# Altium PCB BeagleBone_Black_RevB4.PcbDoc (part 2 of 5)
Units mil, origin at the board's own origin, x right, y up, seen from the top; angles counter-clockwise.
Board outline 3401 x 2151 mil, 6 copper layers (TOP, LYR2_GND, LYR3, LYR4, LYR5_PWR, BOTTOM), stack 62 mil thick; 381 components, 310 nets, 1705 pads, 850 vias.
Unrouted connection lines stored in the file: 1.
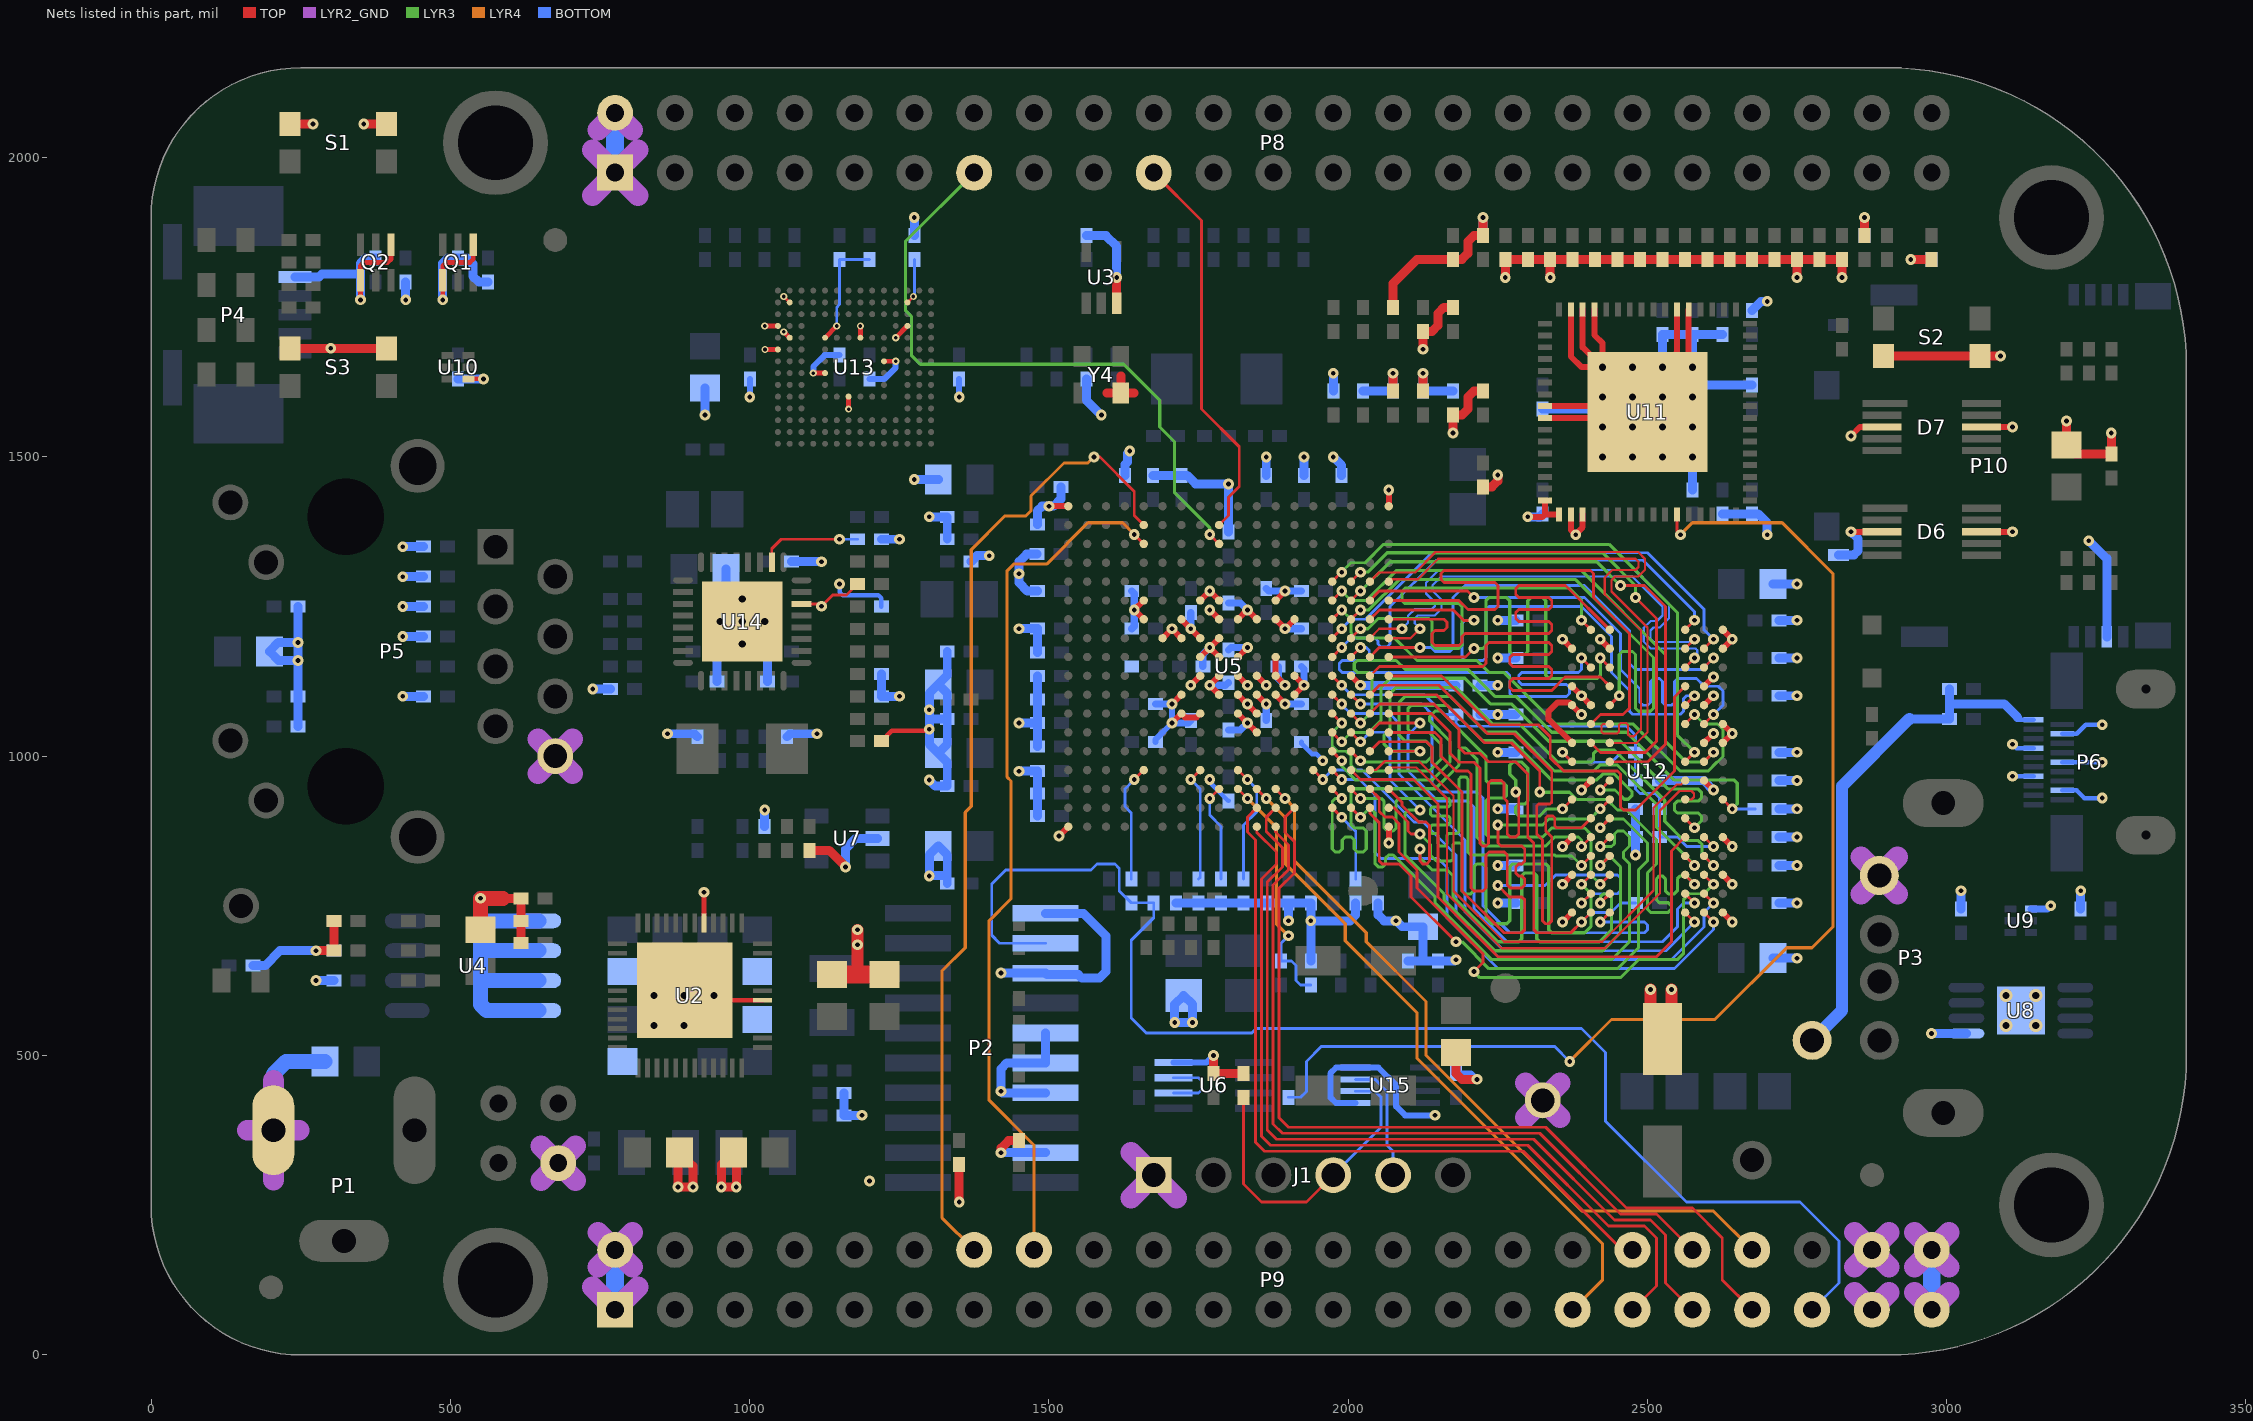
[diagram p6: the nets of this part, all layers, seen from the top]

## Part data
C1 C2 C118 C122 C126 C133: library part CAP_4.7uF_X5R_6.3V_10%_0603, "CAP CER 10UF 10V Y5V 0805"
C3: library part CAP_10uF_Y5V_10V_10%_0805, "CAP CER 0.1UF 6.3V 10% X5R 0402"
C4 C7 C8 C9 C10 C11 C12 C13 C14 C15 C39 C40 C55 C62 C77 C95 C96 C153: library part CAP_10uF_Y5V_10V_10%_0805, "CAP CER 10UF 10V Y5V 0805"
C16 C17 C18: library part CAP_2.2uF_X5R_6.3V_10%_0402, "CAP CER 2.2UF 6.3V 10% X5R 0402"
C19: library part CAP_2.2uF_X5R_6.3V_10%_0402, "CAP CER 470PF 50V 10% X7R 0402"
C20 C27 C28 C29 C30 C31 C33 C35 C36 C37 C38 C41 C42 C43 C44 C45 C46 C47 C48 C49 C50 C51 C52 C53 C54 C56 C57 C58 C59 C60 C61 C63 C64 C65 C66 C67 C68 C69 C70 C71 C72 C73 C74 C75 C76 C78 C79 C80 C81 C82 C83 C84 C85 C86 C87 C88 C92 C93 C94 C97 C98 C99 C100 C101 C102 C103 C105 C106 C131 C132 C135 C152 C154 C155 C158 C159: library part "CAP_0.1uF_X7R_16V_10% 0402", "CAP CER 0.1UF 6.3V 10% X5R 0402"
C21 C22 C25 C26: library part CAP_18PF_COG_50V_5%_0402, "CAP CER 18PF 50V 5% NP0 0402"
C24 C89 C90 C91 C104 C134: library part CAP_1.0UF_X5R_10V_10%_0402, "CAP CER 1UF 10V 10% X5R 0402"
C32: library part CAP_0.001_X7R_50V_5%_0402, "CAP CER 1000PF 16V 10% X7R 0402"
C34: library part "CAP SMD", "CAP ALUM 100UF 6.3V 20% SMD"
C107 C108 C109 C110 C111 C112 C113 C114 C115 C116 C117 C119 C120 C121 C124: library part CAP_0.01uf_X7R_16V_10%_0402, "CAP CER 0.1UF 6.3V 10% X5R 0402"
C123: library part "CAP SMD", "CAP CER 1000PF 16V 10% X7R 0402"
C125 C144 C146 C148 C151: library part "CAP SMD", "CAP CER 2.2UF 6.3V 10% X5R 0402"
C127 C128 C129 C130 C145 C147 C149 C150: library part "CAP SMD", "CAP CER 0.1UF 6.3V 10% X5R 0402"
C136: library part 470pF/5%/50V/C0G/0603_0, "CAP CER 470PF 50V 10% X7R 0402"
C137 C138 C139 C140: library part CAP_0402_100pF_COG_50V, "CAP CER 15PF 50V 5% NP0 0402"
C141: library part CAP_0402_0.1uf_X5R_10V, "CAP CER 0.022UF 10V 10% X7R 0402"
C142 C143: library part CAP_30PF_COG_50V_5%_0402, "CAP CER 30PF 50V 5% NP0 0402"
C156 C157 C160 C161 C162 C163 C164 C165 C166 C167 C168 C169 C170 C171 C172 C173: library part "CAP SMD", "CAP CER 47PF 50V 5% NP0 0402"
D1 D2 D3 D4 D5: library part LED_LTST-C150GKT, "LED GREEN CLEAR 0805 SMD"
D6 D7: library part 32CTQ030/TO_1, "DIODE ESD PROT HDMI 10TSSOP"
D8: library part Zener, "DIODE SCHOTTKY 40V 120MA SOD323"
FB1 FB2 FB3 FB4 FB7: library part FER_180_200_0, "FERRITE 800MA 150 OHM 0805 SMD"
FB5: library part IND, "FERRITE 800MA 150 OHM 0805 SMD"
FB8: library part FER_180_200_0, "RES .10 OHM 1/8W 5% 0805"
J1: library part HDR_6x1, "CONN HEADER 6POS, VERTICAL,  .100 STR TIN"
L1: library part IND_2.2uH_2.6A_10%_SMD, "Inductor 2.2uH smt 2.6A, 58 milliohm"
L2 L3: library part IND_2.2uH_2.6A_10%_SMD, "INDUCTOR 2.2UH 20% 1300MA 1008"
P1: library part Power_Jack, "CONN PWR JACK 2.1X5.5MM HIGH CUR"
P2: library part HDR_10x2_CJTAG, "Dual Line Header 10x2pin Tin"
P3: library part CONN_54819-0578_2, "CONN RCPT USB TYPE A R/A PCB"
P4: library part MINI-USB-AB-SOCKET, "CONN RCPT USB MINI B R/A SMD"
P5: library part CONN_RJ45_MAG_WE_0, "WE-RJ45 LAN Transformer"
P6: library part "Micro HDMI", "CONN HDMI RECPT 19POS SMT R/A"
P8 P9: library part HDR_46_F_2_0.1_0.1, "CONN HEADER FMAL 46PS.1\" DL GOLD"
P10: library part microSD_CONN_2, "CONN MICRO SD R/A PUSH-PUSH SMD"
Q1 Q2: library part RN1907, "TRANS PREBIASED DUAL NPN SOT363"
R1 R55 R56 R57 R58 R59 R60 R61 R62 R63 R64 R65 R66 R67 R68 R69 R70 R76 R77 R78 R79 R80 R81 R82 R83 R84 R85 R86 R87 R88 R89 R90 R91 R92 R93 R94 R95 R165: library part RES_100K_1/16W_1%_0402, "RES 100K OHM 1/16W 1% 0402 SMD"
R3 R4 R119: library part RES_1.5K_1/16W_5%_0402, "RES 1.50K OHM 1/16W 1% 0402 SMD"
R5 R6 R7 R8 R9 R19 R20 R27 R49 R50 R51 R137 R140 R142 R159 R160 R161 R162: library part RES_0_1/16W_1%_0402, "RES 0.0 OHM 1/16W 0402 SMD"
R10: library part RES_470_1/10W_5%_0402, "RES 470K OHM 1/16W 1% 0402 SMD"
R11: library part RES_470_1/10W_5%_0402, "RES 280K OHM 1/16W 1% 0402 SMD"
R12 R71 R72 R73 R74: library part RES_470_1/10W_5%_0402, "RES 820 OHM 1/10W 5% 0402 SMD"
R14 R54 R96 R98 R100 R101 R102 R103 R104 R105 R106 R107 R108 R109 R110 R111 R115 R116 R117 R118 R135 R145 R150 R151 R152 R153 R154 R155 R156 R157: library part RES_10K_1/16W_1%_0402, "RES 10K OHM 1/16W 5% 0402 SMD"
R17: library part RES_1M_1/16W_1%_0402, "Resistor 1Mohm 1/16W 1% 0402"
R18 R21 R28 R45 R46 R47 R48 R167: library part RES_33_0402, "RES 33 OHM 1/16W 5% 0402 SMD"
R22 R120 R121 R122 R123: library part RES_4.7K_0402, "RES 49.9 OHM 1/16W 1% 0402 SMD"
R23 R24 R25: library part RES_4.7K_0402, "RES 4.75K 1/16W 1% 0402 SMD"
R26 R163 R164: library part RES_4.75K_1/16W_1%_0402, "RES 4.75K OHM 1/16W 1% 0402 SMD"
R52 R53 R148 R158: library part "RES SMD", "RES 10K OHM 1/16W 5% 0402 SMD"
R75: library part "RES SMD", "RES 100 OHM 1/10W 5% 0402 SMD"
R97 R112 R113 R114: library part RES_10K_1/16W_1%_0402, "RES 1.50K OHM 1/16W 1% 0402 SMD"
R99: library part RES_10K_1/16W_1%_0402, "RES 240 OHM 1/10W 5% 0402 SMD"
R124: library part RES_10K_1/16W_1%_0402, "Resistor 10Kohm 1/16W 1% 0402"
R125 R126 R129 R134 R138: library part 100-1/10W-1%-0603_4, "RES 100 OHM 1/10W 5% 0402 SMD"
R127 R128 R131 R133 R139: library part RES_100_1/10W_5%_0402, "RES 100 OHM 1/10W 5% 0402 SMD"
R130 R132: library part RES_470_1/10W_5%_0402, "RES 470 OHM 1/10W 5% 0402 SMD"
R136: library part RES_0.1_0805, "RES .10 OHM 1/8W 5% 0805"
R141: library part RES_1M_1/16W_1%_0402, "RES 1M OHM 1/16W 1% 0402 SMD"
R143: library part RES_10K_1/16W_1%_0402, "RES 10 OHM 1/16W 1% 0402 SMD"
R144: library part RES_12.1K_1/16W_1%_0402, "RES 12.1K OHM 1/16W 1% 0402 SMD"
R146 R147: library part "RES SMD", "RES 1.50K OHM 1/16W 1% 0402 SMD"
R149: library part "RES SMD", "RES 0.0 OHM 1/16W 0402 SMD"
R166: library part "RES SMD", "RES 27.0K OHM 1/16W 1% 0402 SMD"
RT1: library part PTC, "POLYSWITCH PTC RESET 0.1A"
S1 S2 S3: library part KMR2, "Microminiature Tact Switch for SMT"
U2: library part PWR_TPS65217_2, "IC PMIC BATT PWR SYST 48VQFN"
U3: "IC INVERTER SINGLE 1INPUT SC705"
U4: "IC LDO VOLT REG 500MA 8-SOIC"
U5: "SubArctic Cortex A8 Processor 15x15"
U6: "SINGLE  POSITIVE-EDGE-TRIGGERED  D-TYPE  FLIP-FLOP WITH  CLEAR  AND  PRESET"
U7: "IC EEPROM 32KBIT 400KHZ SOT23-5"
U8: library part TPS2061_0, "IC 1.5A PWR DIST SWITCH 8-SOIC"
U9 U10: library part PROT_TPD4S012, "ESD 4channel USB Interface"
U11: "IC HDMI TRANSMITTER 64-HVQFN"
U12: library part MT41K256M16HA, "DDR2 SDRAM 2Gb (256Mx8)"
U13: library part eMMC, "Flash Card 2G-byte 3.3V MultiMedia Card 153-Pin WFBGA"
U14: library part "LAN8710 QFN32_1", "Ethernet ICs 10/100 Ethernet XCVR w/HPAutoMDIX FlexPwr"
U15: "IC BUFF/DVR TRI-ST DL 8VSSOP"
Y1: library part CRYS_32_768KHz_SMD32, "CRYSTAL 32.768KHZ 12.5PF SMD"
Y2: library part CRYS_24MHz_SCC, "CRYSTAL 24.000MHZ 18PF SMD"
Y3: library part "Suntsu ITEMP 25MHz _0.005% 20pf"
Y4: library part ASDMB

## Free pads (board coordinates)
  round 40 all layers, no hole mask+40: 1(200,112.5) 1(675,1862.5) 1(2875,300)

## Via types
v1: diameter 18, hole 8, TOP to BOTTOM, tented both sides, 793 vias
v2: diameter 22, hole 12, TOP to BOTTOM, tented both sides, 30 vias
v3: diameter 12, hole 6, TOP to BOTTOM, tented both sides, 27 vias

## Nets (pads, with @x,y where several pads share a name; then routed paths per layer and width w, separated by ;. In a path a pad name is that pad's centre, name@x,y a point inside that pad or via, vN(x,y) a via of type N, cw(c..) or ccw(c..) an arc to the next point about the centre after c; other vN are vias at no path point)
12M_LOOP: U6.2 U6.3 | length 113.7
  BOTTOM w4.75: U6.2@1708,437.2 1750,437.2 1755,442.2 1755,457.8 1750,462.8 U6.3@1708,462.8
12MHZ: R21.2 U11.27 | length 2002.7
  TOP w4.75: U11.27@2549.21,1403.74 2549.21,1375.79 v1(2555,1370)
  LYR4 w5.25: v1(2370,490) 2440,560 2612.5,560 2732.5,680 2775,680 2810,715 2810,1305 2725,1390 2575,1390 v1(2555,1370)
  BOTTOM w4.75: R21.2@1900,430 1920,430 1930,440 1930,490 1955,515 2345,515 v1(2370,490)
AIN0: P9.39 U5.B6 | length 1506.2
  TOP w4.75: U5.B6@1910.24,913.78 1894.51,898.05 1894.51,872.49 1910,857 1910,805 1884.26,779.26 1884.26,395.74 1900,380 2330,380 2465,245 2575,245 2625,195 2625,125 P9.39@2675,75
AIN1: P9.40 U5.C7 | length 1229
  TOP w4.75: U5.C7@1878.74,945.28 v1(1894.5,929.5)
  LYR4 w5.25: v1(1894.5,929.5) 1910,914 1910,825 2019.01,715.99 2019.12,715.99 2030,705.11 2030,690 2130,590 2130,500 2390,240 2610,240 P9.40@2675,175
AIN2: P9.37 U5.B7 | length 1448.2
  TOP w4.75: U5.B7@1878.74,913.78 1862.97,898.01 1862.97,874.03 1890,847 1890,815 1864.76,789.76 1864.76,375.24 1880,360 2310,360 2445,225 2505,225 2530,200 2530,120 P9.37@2575,75
AIN3: P9.38 U5.A7 | length 1304
  TOP w4.75: U5.A7@1878.74,882.28 1878.74,873.26 1900.25,851.75 1900.25,810.25 1874.51,784.51 1874.51,385.49 1890,370 2320,370 2455,235 2515,235 P9.38@2575,175
AIN4: P9.33 U5.C8 | length 1130.3
  TOP w4.75: U5.C8@1847.24,945.28 v1(1863,929.5)
  LYR4 w5.25: v1(1863,929.5) 1895,897.5 1895,820 1995,720 1995,691.51 2115,571.51 2115,495 2425,185 2425,125 P9.33@2375,75
AIN5: P9.36 U5.B8 | length 1275.4
  TOP w4.75: U5.B8@1847.24,913.78 1831.51,898.05 1831.51,873.49 1845,860 1845,355 1860,340 2292.86,340 2457.86,175 P9.36@2475,175
AIN6: P9.35 U5.A8 | length 1408.2
  TOP w4.75: U5.A8@1847.24,882.28 1847.24,872.76 1880,840 1880,820 1855,795 1855,365 1870,350 2300,350 2435,215 2495,215 2515,195 2515,115 P9.35@2475,75
AIN7: R163.2 R164.1 U5.C9 | length 409.1
  TOP w4.75: U5.C9@1815.75,945.28 v1(1831.5,929.5)
  LYR4 w5.25: v1(1831.5,929.5) 1880,881 1880,720 v1(1900,700)
  BOTTOM w4.75: v1(1900,700) 1887.5,687.5 R163.2@1887.5,657.5 1905,657.5 1912.5,650 1912.5,625 1920,617.5 R164.1@1937.5,617.5
B_UART0_RX: J1.4 R165.1 U15.2 | length 536.4
  TOP w4.75: R165.1@1825,430 1825,285 1855,255 1930,255 J1.4@1975,300
  BOTTOM w4.75: J1.4@1975,300 2055,380 2055,430 2044.8,440.2 U15.2@2012,440.2
B_UART0_TX: J1.5 U15.3 | length 205.3
  BOTTOM w4.75: U15.3@2012,459.8 2045.2,459.8 2065,440 2065,350 2075,340 J1.5@2075,300
CAP_VBB_MPU: C91.1 U5.C10 | length 164.7
  TOP w4.75: v1(1768.5,929.5) 1768.98,930 U5.C10@1784.25,945.28
  BOTTOM w4.75: v1(1768.5,929.5) 1768.5,901.5 1787.5,882.5 C91.1@1787.5,795
CAP_VDD_SRAM_CORE: C89.1 U5.D9 | length 204
  TOP w4.75: U5.D9@1815.75,976.77 v1(1831.5,961)
  BOTTOM w4.75: C89.1@1825,795 1825,885 1847.25,907.25 1847.25,945.25 v1(1831.5,961)
CAP_VDD_SRAM_MPU: C90.1 U5.D11 | length 196
  TOP w4.75: v1(1737,961) U5.D11@1752.76,976.77
  BOTTOM w4.75: v1(1737,961) 1752.76,945.24 1752.76,797.76 C90.1@1750,795
CLKOUT2: P2.18 P9.41 R19.2 R20.1 | length 2266.5
  BOTTOM w4.75: P2.18@1494,687.5 1417.5,687.5 1404.26,700.74 1404.26,786.52 1427.74,810 1570,810 1580,820 1610,820 1617.5,812.5 1617.5,775 R19.2@1637.5,755 R20.1@1675,755 1675,730 1637.5,692.5 1637.5,562.5 1662.5,537.5 1838.71,537.5 1846.21,545 2390,545 2430,505 2430,390 2565,255 2755,255 2820,190 2820,120 P9.41@2775,75
CLKOUT_SRC: R19.1 U5.D14 | length 199.3
  TOP w4.75: v1(1642.5,961) U5.D14@1658.27,976.77
  BOTTOM w4.75: R19.1@1637.5,795 1637.5,905 1626.74,915.76 1626.74,945.24 v1(1642.5,961)
CRS: R139.2 U14.14 | length 110.4
  TOP w4.75: U14.14@1086.5,1254.55 1116.04,1254.55 v1(1120,1250.59) 1138.67,1269.26 1161.76,1269.26 R139.2@1180,1287.5
DDR_A0: U5.F3 U12.N3 | length 920.1
  TOP w4.75: U5.F3@2004.72,1039.76 v1(2020.5,1024)
  LYR3 w5.25: v1(2120,910) 2100,910 2095,905 2095,835 2160,770 2160,760 2245,675 2425,675 2455,705 2455,815 2440,830 2433.75,830 v1(2421.25,817.5)
  BOTTOM w4.75: v1(2020.5,1024) 2036.5,1040 2060,1040 2070,1030 2070,960 v1(2120,910)
DDR_A1: U5.H1 U12.P7 | length 924.8
  TOP w4.75: U5.H1@2067.72,1102.76 2147.24,1102.76 2227.5,1022.5 2272.5,1022.5 2320,975 v1(2320,940)
  LYR3 w4.75: 2370,939.75 2381.99,927.76 2428.1,927.76
  LYR3 w5.25: v1(2320,940) 2320.25,939.75 2370,939.75 ; 2428.1,927.76 2432.24,927.76 2450,910 2465,910 2515,860 2515,820 2500,805 2500,743.99 2505,738.99 2535,738.99 2540,743.99 2540,750 2535,755 2520,755 2515,760 2515,795 2520,800 2525,800 2530,795 2530,775 2535,770 2545,770 2550,775 2550,795 2555,800 2564.75,800 v1(2578.75,786)
DDR_A2: U5.E4 U12.P3 | length 919.5
  TOP w4.75: U5.E4@1973.23,1008.27 v1(1989,992.5)
  LYR3 w4.75: 2405.51,869.49 2405.51,801.74 v1(2421.25,786)
  LYR3 w5.25: v1(1989,992.5) 1989,983.61 2012.61,960 2140,960 2170,990 2170,1025 2136.04,1058.96 2136.04,1066.04 2145.75,1075.75 2154.25,1075.75 2230,1000 2230,960 2235,955 2260,955 2264.01,950.99 2264.01,934.01 2260,930 2235,930 2230,925 2230,870 2235,865 2325,865 2340,880 2395,880 2405.51,869.49
DDR_A3: U5.C3 U12.N2 | length 921.3
  TOP w4.75: U5.C3@2004.72,945.28 v1(2020.5,929.5)
  LYR3 w4.75: 2346.76,833.24 2374.01,833.24 v1(2389.75,817.5)
  LYR3 w5.25: v1(2020.5,929.5) 2055,929.5 2060,924.5 2060,880 2065,875 2075,875 2080,880 2080,924.5 2085,929.5 2167,929.5 2170,926.5 2170,918 2167,915 2140.5,915 2137.5,912 2137.5,903 2140.5,900 2167,900 2170,897 2170,888 2167,885 2140.5,885 2137.5,882 2137.5,873.99 2140.5,870.99 2147,870.99 2150,867.99 2150,853 2153,850 2162,850 2165,853 2165,867.99 2168,870.99 2182,870.99 2185,873.99 2185,962 2188,965 2197,965 2200,962 2200,840 2205,835 2345,835 2346.76,833.24
DDR_A4: U5.C2 U12.P8 | length 918.9
  TOP w4.75: U5.C2@2036.22,945.28 2051.85,929.65 2051.85,907.55 2061.25,898.15 2073.95,898.15 2085,887.1 2085,840 2115,810 2115,780 2225,670 2225,655 v1(2210,640)
  LYR3 w4.75: 2570.24,770.24 2594.49,770.24 v1(2610.25,786)
  LYR3 w5.25: v1(2210,640) 2220,630 2455,630 2485,660 2550,660 2560,670 2560,760 2570.24,770.24
DDR_A5: U5.B1 U12.P2 | length 920.5
  TOP w4.75: U5.B1@2067.72,913.78 2076.22,913.78 2100,890 2100,875 2105,870 v1(2120,870)
  LYR3 w4.75: v1(2389.75,786) 2405.49,770.26 2405.49,715.49 2405,715
  LYR3 w5.25: v1(2120,870) 2137.5,852.5 2137.5,834.75 2147.25,825 2172,825 2175,828 2175,852 2178,855 2187,855 2190,852 2190,775 2195,770 2205,770 2210,775 2210,815 2215,820 2225,820 2230,815 2230,730 2240,720 2265,720 2270,725 2270,815 2275,820 2330,820 2335,815 2335,710 2340,705 2395,705 2405,715
DDR_A6: U5.D5 U12.R8 | length 924.7
  TOP w4.75: U5.D5@1941.73,976.77 v1(1957.5,961)
  BOTTOM w4.75: v1(1957.5,961) 1973.24,976.74 2023.26,976.74 2110,890 2125,890 2180,835 2180,735 2255,660 2540,660 2594.49,714.49 2594.49,738.74 v1(2610.25,754.5)
DDR_A7: U5.E2 U12.R2 | length 925.5
  TOP w4.75: U5.E2@2036.22,1008.27 2051.98,1024.03 2130.97,1024.03 2140,1015 2140,990 2190,940 2190,775 2260,705 2290,705 2295,710 2295,760 2290,765 2269.01,765 v1(2250,784.01)
  BOTTOM w4.75: v1(2250,784.01) 2329.01,784.01 2346.74,801.74 2450,801.74 2455,796.74 2455,775.24 2450,770.24 2405.49,770.24 v1(2389.75,754.5)
DDR_A8: U5.D4 U12.T8 | length 919.8
  TOP w4.75: U5.D4@1973.23,976.77 v1(1989,961)
  BOTTOM w4.75: v1(1989,961) 2019,961 2045,935 2045,839.01 2054.75,829.26 2150,829.26 2165,814.26 2165,730 2250,645 2545,645 2610.25,710.25 v1(2610.25,723)
DDR_A9: U5.C1 U12.R3 | length 924.4
  TOP w4.75: U5.C1@2067.72,945.28 2090,923 2090,917.74 2117.74,890 2130,890 2135.74,884.26 2135.74,824.61 2131.13,820 2124.61,820 2120,824.61 v1(2120,845)
  LYR3 w5.25: v1(2120,845) 2120,830 2140,810 2165,810 2175,800 2175,765 2250,690 2285,690 2290,695 2290,800 2295,805 2310,805 2315,800 2315,695 2320,690 2420,690 2440,710 2440,765 2435,770 2426.25,770 2421.25,765 v1(2421.25,754.5)
DDR_A10: U5.F4 U12.L7 | length 920.8
  TOP w4.75: U5.F4@1973.23,1039.76 v1(1989,1024)
  LYR3 w4.75: v1(1989,1024) 2004.76,1039.76 2034.76,1039.76
  LYR3 w5.25: 2034.76,1039.76 2055,1060 2055,1115 2070.25,1130.25 2194.75,1130.25 2237.5,1087.5 2272.5,1087.5 2335,1025 2455,1025 2535,945 2585,945 2590,940 2590,930 2585,925 2550,925 2545,920 2545,910 2550,905 2585,905 2590,900 2590,891.75 v1(2578.75,880.5)
DDR_A11: U5.F2 U12.R7 | length 919.5
  TOP w4.75: U5.F2@2036.22,1039.76 2051.99,1055.53 v1(2120,1055.5)
  BOTTOM w4.75: v1(2120,1055.5) 2100,1035.5 2100,975 2150,925 2200,925 2210,915 2210,745 2265,690 2525,690 2550,715 2550,744.5 2560,754.5 v1(2578.75,754.5)
DDR_A12: U5.E3 U12.N7 | length 926
  TOP w4.75: U5.E3@2004.72,1008.27 v1(2020.5,992.5)
  LYR3 w5.25: v1(2020.5,992.5) 2023,990 2130,990 2140,1000 2140,1015 2130,1025 2095,1025 2085,1035 2085,1090 2095,1100 2170,1100 2230,1040 2280,1040 2344.75,975.25 2410.25,975.25 2420,985 2450,985 2515,920 2515,881.25 v1(2578.75,817.5)
DDR_A13: U5.H3 U12.T3 | length 923.7
  TOP w4.75: U5.H3@2004.72,1102.76 v1(2020.5,1087)
  BOTTOM w4.75: v1(2020.5,1087) 2123,1087 2140,1070 2140,955 2155,940 2215,940 2225,930 2225,750 2270,705 2495,705 2500,710 2500,718 2495,723 v1(2421.25,723)
DDR_A14: U5.H4 U12.T7 | length 923.3
  TOP w4.75: U5.H4@1973.23,1102.76 v1(1989,1087)
  BOTTOM w4.75: v1(1989,1087) 1989,1086 2003.76,1071.24 2068.76,1071.24 2085,1055 2085,970 2195,860 2195,740 2260,675 2530.75,675 v1(2578.75,723)
DDR_A15: U5.D3 U12.M7 | length 949.8
  TOP w4.75: U5.D3@2004.72,976.77 2020.58,960.91 2109.09,960.91 2150,920 2150,765 2250,665 2515,665 2540,690 2540,841.75 U12.M7@2563,864.75
DDR_BA0: U5.C4 U12.M2 | length 927.1
  TOP w4.75: U5.C4@1973.23,945.28 v1(1989,929.5)
  LYR3 w4.75: 1973.26,885 1973.26,924.5 1978.26,929.5 v1(1989,929.5) ; 2004.74,885 2004.74,934.77
  LYR3 w5.25: 1973.26,885 1973.26,844.9 1978.16,840 1985.1,840 1990,844.9 1990,860 1995,865 2005,865 2010,860 2010,845 2015,840 2025,840 2030,845 2030,875 2025,880 2009.74,880 2004.74,885 ; 2004.74,934.77 2004.74,940.49 2009.74,945.49 2145.49,945.49 2185,985 2185,1010 2188.79,1013.79 2196.21,1013.79 2215,995 2215,865 2230,850 2330,850 2345,865 2384.75,865 2389.75,860 v1(2389.75,849)
DDR_BA1: U5.E1 U12.N8 | length 926.3
  TOP w4.75: U5.E1@2067.72,1008.27 v1(2120,1008.27)
  LYR3 w5.25: v1(2120,1008.27) 2071.73,1008.27 2060,1020 2060,1035 2070,1045 2070,1105 2080,1115 2180,1115 2241.49,1053.51 2286.49,1053.51 2350,990 2405,990 2410,995 2410,1005 2415,1010 2445,1010 2528.88,926.12 2528.88,891.12 2561.13,858.87 2585,858.87 2591.38,852.49 2591.38,836.37 v1(2610.25,817.5)
DDR_BA2: U5.B3 U12.M3 | length 927.2
  TOP w4.75: U5.B3@2004.72,913.78 v1(2020.5,898)
  LYR3 w5.25: v1(2020.5,898) 2032.5,910 2040,910 2045,905 2045,820 2050,815 2057.5,815 2062.5,820 2062.5,830 2067.5,835 2075,835 2145,765 2145,755 2240,660 2440,660 2470,690 2470,820 2460,830 2460,840 2470,850 2470,865 2460,875 2450,875 2445,870 2445,854 2440,849 v1(2421.25,849)
DDR_CASN: U5.F1 U12.K3 | length 943.2
  TOP w4.75: U5.F1@2067.72,1039.76 2145,1039.76 2155,1029.76 2155,1000 2180,975 2200,975 2205,970 2205,780 2210,775 2225,775 2230,780 2230,835 2235,840 2260.74,840 2265.74,835 2265.74,785 2270.74,780 2290,780 2295,785 2295,795 2290,800 2285,800 2280,805 2280,815 2285,820 2290,820 2295,825 2295,845 2290,850 2255,850 2250,855 v1(2250,885) ; v1(2421.25,912) U12.K3@2437,927.75
  LYR3 w5.25: v1(2250,885) 2325,885 2335,895 2404.25,895 v1(2421.25,912)
DDR_CKE: R96.2 U5.G3 U12.K9 | length 965.7
  TOP w4.75: U5.G3@2004.72,1071.26 v1(2020.5,1055.5)
  LYR3 w5.25: v1(2020.5,1055.5) 2040,1075 2040,1135 2035,1140 2015,1140 2010,1145 2010,1155 2015,1160 2080,1160 2095,1145 2200,1145 2245,1100 2280,1100 2340,1040 2465,1040 2545,960 2645,960 2650,955 2650,920.25 v1(2641.75,912)
  BOTTOM w4.75: v1(2641.75,912) R96.2@2680,912
DDR_CLK: U5.D2 U12.J7 | length 944.2
  TOP w3.75: U5.D2@2036.22,976.77 2046.32,976.77 2061.55,992 2118,992 2176,934 2176,774.56 2260.56,690 2424.44,690 2510,775.56 2510,914 2548.78,952.78 2556.53,952.78 U12.J7@2563,959.25
DDR_CLKN: U5.D1 U12.K7 | length 944.2
  TOP w3.75: U5.D1@2067.72,976.77 2071.95,981 2113.44,981 2165,929.44 2165,770 2256,679 2429,679 2521,771 2521,909.44 2553.34,941.78 2573.65,941.78 2577.76,937.67 2577.76,931.86 2573.65,927.75 U12.K7@2563,927.75
DDR_CSN: U5.H2 U12.L2 | length 940.2
  TOP w4.75: U5.H2@2036.22,1102.76 2051.98,1118.52 2151.48,1118.52 2232.5,1037.5 2277.5,1037.5 2340,975 2340,923 2337,920 2318,920 2315,917 2315,869.75 2324.75,860 2324.75,725 2329.75,720 2335,720 2340,725 2340,865 2330,875 2330,897 2333,900 2342,900 2345,897 2345,883.38 2348,880.38 2389.63,880.38 U12.L2@2405.5,896.25
DDR_D0: U5.M3 U12.E3 | length 896.1
  TOP w4.75: U5.M3@2004.72,1228.74 v1(2020.5,1244.5)
  LYR3 w5.25: v1(2020.5,1244.5) 2034.5,1244.5 2085,1295 2380,1295 2510,1165 2510,1080 2505,1075 2485,1075 2480,1080 2480,1170 2475,1175 2457.75,1175 2452.75,1170 v1(2452.75,1101)
DDR_D1: U5.M4 U12.F7 | length 896.4
  TOP w4.75: U5.M4@1973.23,1228.74 v1(1989,1244.5)
  LYR3 w4.75: v1(1989,1244.5) 2004.76,1228.74 2004.76,1206.48 2014,1197.24 2077.76,1197.24 ; v1(2578.75,1069.5) 2594.49,1053.76 2616.75,1053.76 2625.99,1044.52 2625.99,1013.37 2626.01,999.65 2616.87,990.51
  LYR3 w5.25: 2077.76,1197.24 2115,1160 2215,1160 2235,1140 2260,1140 2346.49,1053.51 2476.49,1053.51 2554.75,975.25 2601.61,975.25 2616.87,990.51
DDR_D2: U5.N1 U12.F2 | length 918.8
  TOP w4.75: U5.N1@2067.72,1260.24 2184.76,1260.24 2200,1245 2245,1245 2250,1250 2250,1285 2245,1290 2160,1290 2155,1295 2155,1305 2160,1310 2405,1310 2410,1305 2410,1265 2469.75,1205.25 2469.75,1080 2459.37,1069.62 2440.1,1069.62 2440,1069.52 2421.27,1069.52 U12.F2@2405.5,1053.75
DDR_D3: U5.N2 U12.F8 | length 895.9
  TOP w4.75: U5.N2@2036.22,1260.24 2051.95,1275.97 2199.03,1275.97 v1(2210,1265)
  BOTTOM w4.75: v1(2210,1265) 2395,1265 2455,1205 2455,1145 2487.5,1112.5 2487.5,1090 2492.5,1085 2500,1085 2505,1090 2505,1125 2510,1130 2520,1130 2525,1125 2525,1090 2530,1085 2540,1085 2545,1090 2545,1125 2550,1130 2581.74,1130 2595,1116.74 2618.26,1116.74 2625.99,1109.01 2625.99,1085.24 v1(2610.25,1069.5)
DDR_D4: U5.N3 U12.H3 | length 918.3
  TOP w4.75: U5.N3@2004.72,1260.24 v1(2020.5,1276) ; U12.H3@2437,990.75 2500.75,990.75 2530,1020 2530,1250 2495,1285 v1(2455,1285)
  LYR3 w5.25: v1(2020.5,1276) 2021,1276 2070,1325 2415,1325 v1(2455,1285)
DDR_D5: U5.N4 U12.H8 | length 895
  TOP w4.75: U5.N4@1973.23,1260.24 v1(1989,1276)
  LYR3 w4.75: v1(1989,1276) 2004.76,1260.24 2030.24,1260.24
  LYR3 w5.25: 2030.24,1260.24 2080,1310 2390,1310 2530,1170 2530,1025 2565,990 2593.75,990 v1(2610.25,1006.5)
DDR_D6: U5.P3 U12.G2 | length 916.3
  TOP w4.75: U5.P3@2004.72,1291.73 v1(2020.5,1307.5) ; U12.G2@2405.5,1022.25 2421.37,1006.38 2496.38,1006.38 2515,1025 2515,1230 v1(2480,1265)
  LYR3 w5.25: v1(2020.5,1307.5) 2032.5,1307.5 2065,1340 2425,1340 2480,1285 v1(2480,1265)
DDR_D7: U5.P4 U12.H7 | length 895.2
  TOP w4.75: U5.P4@1973.23,1291.73 v1(1989,1307.5)
  LYR3 w4.75: v1(1989,1307.5) 2004.76,1323.26 2028.26,1323.26
  LYR3 w5.25: 2028.26,1323.26 2059.01,1354.01 2435.99,1354.01 2550,1240 2550,1035.25 v1(2578.75,1006.5)
DDR_D8: U5.J1 U12.D7 | length 799
  TOP w4.75: U5.J1@2067.72,1134.25 2155.75,1134.25 2237.5,1052.5 2317.5,1052.5 2337.5,1032.5 2337.5,997.5 2360,975 2450,975 2455,970 2455,915 2460,910 2480,910 2545,975 2545,1098.75 U12.D7@2563,1116.75
DDR_D9: U5.K1 U12.C3 | length 799.4
  TOP w4.75: U5.K1@2067.72,1165.75 2195.74,1165.74 v1(2210,1180) ; v1(2421.25,1164) U12.C3@2437,1148.25
  LYR3 w5.25: v1(2210,1180) 2225,1180 2230,1185 2230,1260 2235,1265 2265,1265 2270,1260 2270,1175 2275,1170 2295,1170 2300,1175 2300,1260 2305,1265 2325,1265 2330,1260 2330,1135 2335,1130 2416.25,1130 2421.25,1135 v1(2421.25,1164)
DDR_D10: U5.K2 U12.C8 | length 776.7
  TOP w4.75: U5.K2@2036.22,1165.75 2051.95,1181.48 v1(2120,1181.48)
  BOTTOM w4.75: v1(2120,1181.48) 2138.52,1181.48 2145,1175 2170,1175 2175,1180 2175,1265 2195,1285 2395,1285 2470,1210 2470,1155 2480,1145 2591.25,1145 v1(2610.25,1164)
DDR_D11: U5.K3 U12.C2 | length 774.8
  TOP w4.75: U5.K3@2004.72,1165.75 v1(2020.5,1181.5)
  BOTTOM w4.75: v1(2020.5,1181.5) 2030,1181.5 2035,1176.5 2035,1165 2030,1160 1990,1160 1985,1155 1985,1145 1990,1140 2265,1140 2270,1135 2270,1105 2275,1100 2365,1100 2370,1105 2370,1115 2365,1120 2290,1120 2285,1125 2285,1135 2290,1140 2384.75,1140 2389.75,1145 v1(2389.75,1164)
DDR_D12: U5.K4 U12.A7 | length 774.1
  TOP w4.75: U5.K4@1973.23,1165.75 v1(1989,1181.5)
  BOTTOM w4.75: v1(1989,1181.5) 2004.76,1197.26 2045,1197.26 2050,1192.26 2050,1187.5 2055,1182.5 2065,1182.5 2070,1187.5 2070,1250 2147.5,1327.5 2492.5,1327.5 2578.75,1241.25 v1(2578.75,1227)
DDR_D13: U5.L3 U12.A2 | length 774.1
  TOP w4.75: U5.L3@2004.72,1197.24 v1(2020.5,1213)
  LYR3 w5.25: v1(2020.5,1213) 2033,1213 2050,1230 2135,1230 2140,1225 2140,1185 2145,1180 2185,1180 2190,1185 2190,1250 2185,1255 2095,1255 2090,1260 2090,1275.99 2095,1280.99 2369.01,1280.99 2390,1260 2390,1227.25 v1(2389.75,1227)
DDR_D14: U5.L4 U12.B8 | length 776.1
  TOP w4.75: U5.L4@1973.23,1197.24 v1(1989,1213)
  BOTTOM w4.75: v1(1989,1213) 2004.76,1228.76 2028.76,1228.76 2140,1340 2500,1340 2594.49,1245.51 2594.49,1211.26 v1(2610.25,1195.5)
DDR_D15: U5.M1 U12.A3 | length 792.6
  TOP w4.75: U5.M1@2067.72,1228.74 2100,1228.74 2160,1228.75 2165,1223.75 2165,1215 2160,1210 2145,1210 2140,1205 2140,1190 2145,1185 2185,1185 2190,1190 2190,1200 2195,1205 2335,1205 2340,1210 2340,1220 2335,1225 2285,1225 2280,1230 2280,1240 2285,1245 2335,1245 2340,1250 2340,1260 2335,1265 2285,1265 2280,1270 2280,1280 2285,1285 2363.25,1285 U12.A3@2437,1211.25
DDR_DQM0: U5.M2 U12.E7 | length 896.9
  TOP w4.75: U5.M2@2036.22,1228.74 2051.99,1244.51 2175.49,1244.51 2193,1227 v1(2210,1227)
  BOTTOM w4.75: v1(2210,1227) 2195,1227 2190,1222 2190,1165 2195,1160 2225,1160 2230,1165 2230,1245 2235,1250 2390,1250 2440,1200 2440,1140 2470,1110 2470,1075 2475,1070 2555,1070 2560,1075 2560,1096 2565,1101 v1(2578.75,1101)
DDR_DQM1: U5.J2 U12.D3 | length 793.8
  TOP w4.75: U5.J2@2036.22,1134.25 2051.97,1150 2225,1150 2230,1155 2230,1185 2235,1190 2335,1190 2340,1185 2340,1175 2335,1170 2275,1170 2270,1165 2270,1155 2275,1150 2335,1150 2340,1145 2340,1135 2335,1130 2275,1130 2270,1125 2270,1115 2275,1110 2340,1110 2362.48,1132.48 2421.27,1132.48 U12.D3@2437,1116.75
DDR_DQS0: U5.P1 U12.F3 | length 915.7
  TOP w3.75: U5.P1@2067.72,1291.73 2071.85,1295.86 2116.42,1295.86 2150.56,1330 2480,1330 2485,1325 2485,1316.24 2480,1311.24 2441.24,1311.24 2428.76,1298.76 2428.76,1270.68 2489,1210.44 2489,1044.56 2477.69,1033.25 2470.5,1033.25 2467.5,1036.25 2467.5,1052.25 2464.5,1055.25 2455.5,1055.25 2452.5,1052.25 2452.5,1041 2449.5,1038 2426,1038 2423,1041 2423,1050.75 2426,1053.75 U12.F3@2437,1053.75
DDR_DQS1: U5.L1 U12.C7 | length 776.1
  TOP w3.75: U5.L1@2067.72,1197.24 2104.23,1197.24 v1(2120,1213)
  BOTTOM w3.75: v1(2120,1213) 2111,1222 2111,1230 2116,1235 2144.56,1235 2156,1246.44 2156,1261.56 2141,1276.56 2141,1285.44 2155.8,1300.24 2474.76,1300.24 2525,1250 2525,1235 2516,1226 2505.44,1226 2494,1214.56 2494,1191.44 2505.44,1180 2580.25,1180 2583.25,1177 2583.25,1167 2580.25,1164 v1(2578.75,1164)
DDR_DQSN0: U5.P2 U12.G3 | length 915.8
  TOP w3.75: U5.P2@2036.22,1291.73 2051.35,1306.86 2111.86,1306.86 2146,1341 2484.56,1341 2496,1329.56 2496,1311.68 2484.56,1300.24 2445.8,1300.24 2439.76,1294.2 2439.76,1275.24 2500,1215 2500,1040 2482.25,1022.25 U12.G3@2437,1022.25
DDR_DQSN1: U5.L2 U12.B7 | length 776.6
  TOP w3.75: U5.L2@2036.22,1197.24 2051.99,1213.01 v1(2090,1213)
  BOTTOM w3.75: v1(2090,1213) 2100,1223 2100,1234.56 2111.44,1246 2140,1246 2145,1251 2145,1257 2130,1272 2130,1290 2151.24,1311.24 2479.32,1311.24 2536,1254.56 2536,1230.44 2520.56,1215 2510,1215 2505,1210 2505,1196 2510,1191 2574.25,1191 v1(2578.75,1195.5)
DDR_ODT: U5.G1 U12.K1 | length 926.9
  TOP w4.75: U5.G1@2067.72,1071.26 2113.47,1071.26 ; 2113.48,1071.27 2138.73,1071.27 2170,1040 2170,1005 2185,990 2210,990 2220,980 2220,854.18 2224.18,850 2230.08,850 2234.26,854.18 2234.26,955 2238.52,959.26 2255.74,959.26 2260,955 2260,930 2265.74,924.26 2265.74,870 2270.74,865 2280,865 2285,870 2285,935 v1(2280,940)
  LYR3 w5.25: v1(2280,940) 2280,960 2270,970 2270,985 2275,990 2290,990 2300,980 2300,925 2295,920 2285,920 2280,915 2280,905 2285,900 2320,900 2332,912 v1(2358.25,912)
DDR_RASN: U5.G4 U12.J3 | length 921.5
  TOP w4.75: U5.G4@1973.23,1071.26 v1(1989,1055.5)
  LYR3 w4.75: v1(1989,1055.5) 1973.26,1039.76 1973.26,1016.74 1981.74,1008.26 1996.74,1008.26 2004.76,1000.24 2004.76,985 2014.76,975 2021,975
  LYR3 w5.25: 2021,975 2135,975 2155,995 2155,1020 2135.49,1039.51 2105,1039.51 2100,1044.51 2100,1080 2105,1085 2165,1085 2224.25,1025.75 2274.25,1025.75 2339.5,960.5 2415.5,960.5 2425,970 2445,970 2473.96,941.04 2473.96,933.96 2468.15,928.15 2461.09,928.15 2445.75,943.5 v1(2421.25,943.5)
DDR_RESETN: R97.2 U5.G2 U12.T2 | length 793.1
  TOP w4.75: U5.G2@2036.22,1071.26 2051.99,1087.03 2142.97,1087.03 2185,1045 2185,1015 2195,1005 2220,1005 2234.26,990.74 2279.26,990.74 2300,970 2300,865 2310,855 2310,710 2315,705 2371.75,705 v1(2389.75,723)
  BOTTOM w4.75: v1(2389.75,723) 2405.51,738.76 2439.26,738.76 2455,754.5 R97.2@2480,754.5
DDR_VREF: C28.1 C123.1 C124.1 R98.2 R100.1 U5.J4 U12.H1 U12.M8 | length 990
  TOP w4.75: U5.J4@1973.23,1134.25 v1(1989,1118.5)
  BOTTOM w4.75: v1(1989,1118.5) 2004.74,1102.76 2127.24,1102.76 2160.5,1069.5 C28.1@2180,1069.5 2180,1055 2185,1050 2465,1050 2480,1035 R98.2@2480,1006.5 ; v1(2358.25,1006.5) 2374.75,990 2440,990 2456.5,1006.5 R98.2@2480,1006.5 ; v1(2610.25,849) 2565.75,849 2550,864.75 C124.1@2520,864.75 R100.1@2520,912 2520,930 2512.5,937.5 2487.5,937.5 2480,945 C123.1@2480,959.25 R98.2@2480,1006.5
DDR_VTP: R22.2 U5.J3 | length 181.8
  TOP w10: U5.J3@2004.72,1134.25 v1(2020.5,1118.5)
  BOTTOM w15: v1(2020.5,1118.5) R22.2@2180,1118.5
DDR_WEN: U5.B2 U12.L3 | length 920.5
  TOP w4.75: U5.B2@2036.22,913.78 2036.22,904.38 2051.85,888.75 2051.85,825 2056.85,820 2085,820 2105,800 2105,765 v1(2180,690)
  LYR3 w5.25: v1(2180,690) 2180.25,689.75 2190.25,689.75 2235,645 2450,645 2485,680 2485,810 2500,825 2500,855 2460,895 2435.75,895 v1(2421.25,880.5)
DGND: C1.1 C2.1 C3.1 C4.1 C7.1 C8.1 C9.1 C10.1 C11.1 C12.1 C13.1 C14.1 C15.1 C16.2 C17.2 C18.2 C19.2 C20.2 C24.2 C27.2 C28.2 C29.2 C30.2 C34.2 C35.2 C36.2 C37.2 C38.2 C39.1 C40.1 C41.2 C42.2 C43.2 C44.2 C45.2 C46.2 C47.2 C48.2 C49.2 C50.2 C51.2 C52.2 C53.2 C54.2 C55.1 C56.1 C57.1 C58.2 C59.2 C60.1 C61.1 C62.1 C63.2 C64.2 C65.2 C66.2 C67.2 C68.1 C69.1 C70.1 C71.1 C72.1 C73.1 C74.1 C75.1 C76.1 C77.2 C78.2 C79.2 C80.2 C81.2 C82.2 C83.2 C84.2 C85.2 C86.2 C87.2 C88.2 C89.2 C90.2 C91.2 C92.2 C94.2 C95.1 C96.1 C97.2 C98.2 C99.2 C100.2 C101.2 C102.2 C103.2 C104.2 C105.2 C106.2 C107.2 C108.2 C109.2 C110.2 C111.2 C112.2 C113.2 C114.2 C115.2 C116.2 C117.2 C118.1 C119.2 C120.2 C121.2 C122.1 C123.2 C124.2 C125.2 C126.1 C127.2 C128.2 C129.2 C130.2 C131.2 C132.2 C133.1 C134.2 C135.2 C136.2 C137.2 C138.2 C139.2 C140.2 C141.2 C142.2 C143.2 C144.2 C145.2 C146.2 C147.2 C148.2 C149.2 C150.2 C151.2 C152.2 C153.2 C154.2 C155.1 C156.2 C157.2 C158.2 C159.2 C160.2 C161.2 C162.2 C163.2 C164.2 C165.2 C166.2 C167.2 C168.2 C169.2 C170.2 C171.2 C172.2 C173.2 D6.3 D6.8 D7.3 D7.8 FB3.2 J1.1 P1.2 P2.4 P2.8 P2.10 P2.12 P2.16 P2.20 P3.4 P4.5 P5.8 P6.4 P6.7 P6.10 P6.13 P6.16 P8.1 P8.2 P9.1 P9.2 P9.43 P9.44 P9.45 P9.46 P10.6 P10.9 Q1.1 Q1.4 Q2.1 Q2.4 R10.2 R12.1 R22.1 R25.2 R49.1 R53.2 R54.1 R76.2 R77.2 R78.2 R79.2 R80.2 R81.2 R82.2 R83.2 R84.2 R85.2 R86.2 R87.2 R88.2 R89.2 R90.2 R91.2 R92.2 R93.2 R94.2 R95.2 R96.1 R99.1 R100.2 R115.2 R116.2 R117.2 R118.2 R130.1 R132.1 R135.2 R136.1 R144.2 R145.2 R148.2 R149.2 R164.2 R165.2 S1.1 S1.3 S2.2 S2.4 S3.1 S3.3 TP1.1 TP8.1 U2.30 U2.41 U2.49 U3.3 U4.5 U4.6 U4.7 U4.8 U5.A1 U5.A18 U5.F8 U5.G8 U5.G9 U5.G11 U5.G12 U5.H6 U5.H7 U5.H8 U5.H9 U5.H10 U5.H12 U5.J6 U5.J7 U5.J8 U5.J9 U5.J10 U5.J11 U5.K7 U5.K9 U5.K10 U5.K11 U5.L10 U5.L11 U5.L12 U5.L13 U5.M6 U5.M7 U5.M8 U5.M9 U5.M10 U5.M12 U5.M14 U5.N7 U5.N10 U5.N11 U5.N14 U5.V1 U5.V18 U6.4 U7.2 U8.1 U8.9 U9.4 U10.4 U11.8 U11.9 U11.16 U11.17 U11.18 U11.19 U11.53 U11.54 U11.61 U11.62 U11.63 U11.65 U12.A9 U12.B1 U12.B3 U12.B9 U12.D1 U12.D8 U12.E1 U12.E2 U12.E8 U12.F9 U12.G1 U12.G8 U12.G9 U12.J2 U12.J8 U12.M1 U12.M9 U12.P1 U12.P9 U12.T1 U12.T9 U13.C4 U13.E7 U13.G5 U13.H10 U13.K8 U13.N2 U13.N5 U13.P4 U13.P6 U14.33 U15.1 U15.4 Y4.2 | length 18513.7
  TOP w4.75: v3(1056.89,1768.11) U13.N2@1066.73,1758.27
  TOP w7.5: U10.4@529.78,1630.32 v1(555,1630.32) ; R118.2@1220,1025 1237.4,1042.4 1297.4,1042.4 v1(1300,1045)
  TOP w8: v1(349.41,1762.5) Q2.1@349.41,1795.47 349.41,1819.41 355,1825 395,1825 400.59,1830.59 Q2.4@400.59,1854.53 ; v1(486.91,1762.5) Q1.1@486.91,1795.47 486.91,1819.41 492.5,1825 532.5,1825 538.09,1830.59 Q1.4@538.09,1854.53 ; U2.41@923.62,721.06 v1(923.62,772.5) ; v2(940,600) 955,600 962.87,592.13 U2.30@1021.06,592.13 ; v3(1025,1718.9) U13.P4@1047.05,1718.9 ; v3(1025.47,1679.53) U13.P6@1047.05,1679.53 ; v3(1056.89,1709.06) U13.N5@1066.73,1699.21 ; v3(1106.1,1640.16) U13.K8@1125.79,1640.16 ; v3(1165.16,1580) U13.H10@1165.16,1600.79 ; U13.G5@1184.84,1699.21 v3(1184.84,1718.9) ; U13.E7@1224.21,1659.84 v3(1243.9,1659.84) ; v3(1243.9,1699.21) U13.C4@1263.58,1718.9
  TOP w10: v1(1500,1417.72) U5.V18@1532.28,1417.72 ; v1(1516.5,866.5) U5.A18@1532.28,882.28 ; U5.M14@1658.27,1228.74 v1(1642.5,1244.5) U5.N14@1658.27,1260.24 ; U5.L13@1689.76,1197.26 v1(1705.5,1213) U5.L12@1721.26,1197.24 ; v1(1705.5,1055.5) U5.G12@1721.26,1071.26 1727.52,1065 1746.5,1065 U5.G11@1752.76,1071.26 ; v1(1705.5,1087) U5.H12@1721.26,1102.76 ; U5.M12@1721.26,1228.74 v1(1737,1213) U5.L11@1752.76,1197.24 ; v1(1737,1118.5) U5.J11@1752.76,1134.25 ; U5.K11@1752.76,1165.76 v1(1768.5,1181.5) ; U5.N11@1752.76,1260.24 v1(1768.5,1276) U5.N10@1784.25,1260.24 ; v1(1768.5,1244.5) U5.M10@1784.25,1228.74 ; U5.H10@1784.24,1102.76 v1(1768.5,1118.5) U5.J10@1784.25,1134.25 ; U5.K10@1784.25,1165.75 v1(1768.5,1181.5) ; U5.L10@1784.24,1197.24 v1(1768.5,1181.5) ; U5.G9@1815.75,1071.26 v1(1831.5,1055.51) U5.F8@1847.24,1039.76 ; U5.H9@1815.75,1102.76 v1(1831.5,1087.01) U5.G8@1847.24,1071.26 ; U5.J9@1815.75,1134.25 v1(1831.5,1118.5) ; U5.K9@1815.75,1165.75 v1(1831.5,1181.5) ; U5.M9@1815.75,1228.74 v1(1831.5,1244.49) U5.M8@1847.24,1228.74 ; U5.H8@1847.24,1102.76 v1(1862.99,1087.01) ; U5.J8@1847.24,1134.25 v1(1862.99,1118.5) ; U5.H7@1878.74,1102.76 v1(1894.5,1087) ; U5.K7@1878.74,1165.75 U5.J7@1878.74,1134.25 v1(1894.5,1118.5) ; U5.M7@1878.76,1228.74 v1(1894.5,1213) U5.M6@1910.24,1228.74 ; U5.N7@1878.74,1260.24 v1(1894.5,1276) ; U5.H6@1910.24,1102.76 v1(1926,1118.5) U5.J6@1910.24,1134.25 ; v1(2067.72,855) U5.A1@2067.72,882.28 ; U5.V1@2067.72,1417.72 v1(2067.72,1445) ; v1(2300,1400) 2325,1400 2328.74,1403.74 ; U11.16@2328.74,1427.36 2328.74,1403.74 ; U11.9@2328.74,1565.16 2409.84,1565.16 v2(2425,1550) ; U11.8@2328.74,1584.84 2409.84,1584.84 v2(2425,1600) ; U11.17@2352.36,1403.74 2328.74,1403.74 ; U11.18@2372.05,1403.74 2372.05,1377.95 v1(2380,1370) 2380,1370.97 2391.73,1382.7 U11.19@2391.73,1403.74 ; U11.63@2372.05,1746.26 2372.05,1667.95 2390,1650 v2(2425,1650) ; U12.G1@2374,1022.25 2335,1061.25 2335,1075 2350,1090 2369.25,1090 U12.E1@2374,1085.25 ; U12.D1@2374,1116.75 v1(2389.75,1101) ; U11.62@2391.73,1746.26 2391.73,1683.27 v2(2425,1650) ; U11.61@2411.42,1746.26 2411.42,1703.58 2425,1690 v2(2425,1650) ; v2(2525,1650) 2549.21,1674.21 U11.54@2549.21,1746.26 ; U11.53@2568.9,1746.26 2568.9,1656.1 v2(2575,1650) ; U12.F9@2626,1053.75 v1(2641.75,1038) ; U12.A9@2626,1211.25 v1(2641.75,1195.5) ; v1(2840,1375) D6.3@2892,1375 ; v1(2840,1535) 2855,1550 D7.3@2892,1550 ; D6.8@3058,1375 v1(3110,1375) ; D7.8@3058,1550 v1(3110,1550)
  TOP w15: S3.3@231.79,1681.5 v1(300,1681.5) S3.1@393.21,1681.5 ; S1.3@231.79,2056.5 v1(270,2056.5) ; v1(275,675) R10.2@305,675 C19.2@305,725 ; v1(355,2056.5) S1.1@393.21,2056.5 ; 587.5,762.5 C3.1@617.5,762.5 C18.2@617.5,725 C16.2@617.5,687.5 ; C37.2@1100,842.5 1132.5,842.5 v1(1160,815) ; v1(1350,255) C29.2@1350,317.5 ; v1(1420,337.5) 1420,345 1432.5,357.5 R25.2@1450,357.5 ; 1597,1607 Y4.2@1620,1607 ; U3.3@1613.09,1756.69 v1(1613.09,1800) ; 1620,1635 Y4.2@1620,1607 ; 1642,1607 Y4.2@1620,1607 ; v1(1775,500) C27.2@1775,470 R165.2@1825,470 ; C166.2@2075,1610 v1(2075,1640) ; C168.2@2075,1750 2075,1790 2115,1830 C165.2@2175,1830 2190,1830 2200,1840 2200,1860 2210,1870 C57.1@2225,1870 v1(2225,1900) ; C157.2@2125,1610 v1(2125,1640) ; v1(2125,1680) C167.2@2125,1710 2140,1710 2150,1720 2150,1740 2160,1750 C156.2@2175,1750 ; v1(2175,1540) C160.2@2175,1570 2190,1570 2200,1580 2200,1600 2210,1610 C163.2@2225,1610 ; C96.1@2180,505 2180,470 2190,460 v1(2215,460) ; C169.2@2225,1450 2240,1450 2250,1460 v1(2250,1470) ; v1(2262.5,1800) R81.2@2262.5,1830 R80.2@2300,1830 R84.2@2337.5,1830 ; v1(2337.5,1800) R84.2@2337.5,1830 ; v1(2750,1800) R93.2@2750,1830 ; v1(2825,1800) R95.2@2825,1830 R94.2@2787.5,1830 R93.2@2750,1830 ; C61.1@2862.5,1870 v1(2862.5,1900) ; S2.4@2894.29,1668.5 S2.2@3055.71,1668.5 v1(3090,1668.5) ; v1(2940,1830) C173.2@2975,1830 ; v1(3200,1560) C153.2@3200,1520 3215,1505 C154.2@3275,1505 v1(3275,1540) ; R84.2@2337.5,1830 R82.2@2375,1830 R83.2@2412.5,1830 R85.2@2450,1830 R86.2@2487.5,1830 R87.2@2525,1830 R88.2@2562.5,1830 R89.2@2600,1830 R90.2@2637.5,1830 R91.2@2675,1830 R92.2@2712.5,1830 R93.2@2750,1830 ; v1(880,280) v1(905,280) 905,315 C9.1@882.5,337.5 880,335 v1(880,280) ; v1(952.5,280) v1(977.5,280) 977.5,332.5 C12.1@972.5,337.5 952.5,317.5 v1(952.5,280)
  TOP w20: 1180,635 v1(1180,685) v1(1180,710) ; v1(2505,610) 2505,547.5 C34.2@2525,527.5 2540,542.5 v1(2540,610)
  TOP w25: C1.1@550,710 v1(550,762.5) 587.5,762.5
  TOP w30: C11.1@1137.5,635 1180,635 C55.1@1225,635
  LYR2_GND w35: 160.98,375 P1.2@204,375 ; 204,291.98 P1.2@204,375 ; 204,458.02 P1.2@204,375 ; 247.02,375 P1.2@204,375 ; 646.12,971.12 P5.8@675,1000 ; 646.12,1028.88 P5.8@675,1000 ; 651.12,291.12 TP8.1@680,320 ; 651.12,348.88 TP8.1@680,320 ; 703.88,971.12 P5.8@675,1000 ; 703.88,1028.88 P5.8@675,1000 ; 708.88,291.12 TP8.1@680,320 ; 708.88,348.88 TP8.1@680,320 ; 736.98,113.02 P9.1@775,75 813.02,113.02 ; 736.98,1936.98 P8.1@775,1975 ; 736.98,2013.02 P8.1@775,1975 ; 746.12,146.12 P9.2@775,175 ; 746.12,203.88 P9.2@775,175 ; 746.12,2046.12 P8.2@775,2075 803.88,2046.12 ; 803.88,146.12 P9.2@775,175 ; 803.88,203.88 P9.2@775,175 ; 813.02,1936.98 P8.1@775,1975 ; 813.02,2013.02 P8.1@775,1975 ; 1636.98,261.98 J1.1@1675,300 ; 1636.98,338.02 J1.1@1675,300 ; 1713.02,261.98 J1.1@1675,300 ; 2296.12,396.12 TP1.1@2325,425 ; 2296.12,453.88 TP1.1@2325,425 ; 2353.88,396.12 TP1.1@2325,425 ; 2353.88,453.88 TP1.1@2325,425 ; 2846.12,103.88 P9.43@2875,75 2903.88,103.88 ; 2846.12,146.12 P9.44@2875,175 ; 2846.12,203.88 P9.44@2875,175 ; 2856.85,769.95 P3.4@2887.5,800.6 ; 2856.85,831.25 P3.4@2887.5,800.6 ; 2903.88,146.12 P9.44@2875,175 ; 2903.88,203.88 P9.44@2875,175 ; 2918.15,769.95 P3.4@2887.5,800.6 ; 2918.15,831.25 P3.4@2887.5,800.6 ; 2946.12,103.88 P9.45@2975,75 3003.88,103.88 ; 2946.12,146.12 P9.46@2975,175 ; 2946.12,203.88 P9.46@2975,175 ; 3003.88,146.12 P9.46@2975,175 ; 3003.88,203.88 P9.46@2975,175
  BOTTOM w7.5: v1(1150,1287.5) 1150,1273.75 1155,1268.75 1215,1268.75 1220,1263.75 R115.2@1220,1250 ; v1(1768.5,961) 1768.5,956.5 1799.75,925.25 C88.2@1800,925.25 ; v1(3110,966.38) P6.7@3145.08,966.38 ; v1(3110,1020) 3116.38,1013.62 P6.13@3145.08,1013.62 ; P6.4@3193.31,942.76 3217.24,942.76 3230,930 v1(3260,930) ; P6.10@3193.31,990 v1(3260,990) ; P6.16@3193.31,1037.24 3217.24,1037.24 3232.5,1052.5 v1(3260,1052.5)
  BOTTOM w8: C100.2@1921.75,1024 1921.75,1021.31 1939.31,1003.75 1946.25,1003.75 v1(1957.5,992.5)
  BOTTOM w10: v1(1000,1600) C127.2@1000,1630 ; v3(1106.1,1640.16) 1106.1,1651.1 1125,1670 C128.2@1150,1670 ; C129.2@1200,1630 1225,1630 1243.9,1648.9 v3(1243.9,1659.84) ; v1(1350,1600) C130.2@1350,1630 ; C70.1@1678.25,1024 1678.25,1028.25 v1(1705.5,1055.5) v1(1705.5,1087) ; U6.4@1708,488.4 1763.4,488.4 v1(1775,500) ; U15.1@2012,420.5 1979.5,420.5 1970,430 1970,470 1979.5,479.5 U15.4@2012,479.5 2050.5,479.5 2080,450 2080,415 2095,400 v1(2145,400) ; C155.1@2180,470 2205,470 v1(2215,460)
  BOTTOM w12: C66.2@1638.25,1213 1642.5,1217.25 v1(1642.5,1244.5) 1642.5,1271.75 C41.2@1638.25,1276 ; C60.1@1678.25,1087 v1(1705.5,1087) ; v1(1705.5,1055.5) 1732.75,1055.5 C63.2@1737,1059.75 ; v1(1737,1213) C94.2@1737,1240.25 ; C46.2@1757,1150 1757,1170 v1(1768.5,1181.5) ; v1(1768.5,1118.5) 1794.6,1118.5 C49.2@1800,1122.75 ; C72.1@1800,1043.98 1819.99,1044 v1(1831.5,1055.51) ; C47.2@1800,1177.25 1804.25,1181.5 v1(1831.5,1181.5) ; C42.2@1800,1256 1819.99,1256 v1(1831.5,1244.49) ; C50.2@1863,1059.75 v1(1862.99,1087.01) ; C43.2@1863,1280.25 1867.25,1276 v1(1894.5,1276) C73.1@1921.75,1276 ; C48.2@1883,1150 1883,1130 v1(1894.5,1118.5) ; v1(1894.5,1087) C99.2@1921.75,1087 ; v1(1894.5,1213) C97.2@1921.75,1213 ; C98.2@1921.72,1150 1925.99,1145.76 v1(1926,1118.5) ; U9.4@3141.18,744.68 3168.58,744.68 v1(3173.9,750)
  BOTTOM w15: R12.1@170,650 190,650 215,675 v1(275,675) C20.2@305,675 ; P4.5@240,1800.49 280,1800.49 284.84,1805.33 349.41,1805.33 ; R135.2@245,1050 R130.1@245,1100 v1(245,1160) ; R132.1@245,1250 v1(245,1190) ; v1(275,625) C17.2@305,625 ; v1(349.41,1762.5) 349.41,1805.33 ; R78.2@375,1832.5 358.43,1832.5 349.41,1823.48 349.41,1805.33 ; v1(420,1100) C140.2@455,1100 ; v1(420,1200) C141.2@455,1200 ; v1(420,1250) C139.2@455,1250 ; v1(420,1300) C138.2@455,1300 ; v1(420,1350) C137.2@455,1350 ; v1(425,1762.5) R79.2@425,1792.5 ; v1(486.91,1762.5) 486.91,1823.48 495.93,1832.5 R76.2@512.5,1832.5 527.5,1832.5 537.5,1822.5 537.5,1802.25 547.25,1792.5 R77.2@562.5,1792.5 ; C36.2@512.5,1630 554.68,1630 v1(555,1630.32) ; v1(737.5,1112.5) R144.2@767.5,1112.5 ; v1(862.5,1037.5) 907.5,1037.5 C142.2@912.5,1032.5 ; v1(925,1570) C126.1@925,1615 ; C131.2@945,1125 C132.2@945,1175 ; v2(950,1225) 945,1220 C132.2@945,1175 ; C133.1@960,1312.5 960,1277.5 975,1262.5 v2(987.5,1262.5) ; C152.2@1025,882.5 v1(1025,910) ; C134.2@1030,1125 C136.2@1030,1175 1000,1175 v2(987.5,1187.5) 975,1175 C132.2@945,1175 ; C143.2@1062.5,1032.5 1067.5,1037.5 v1(1112.5,1037.5) ; C135.2@1070,1325 v1(1120,1325) ; C24.2@1157.5,437.5 C30.2@1157.5,400 v1(1187.5,400) ; v1(1160,815) 1160,845 1177.5,862.5 U7.2@1213.5,862.5 ; R117.2@1220,1137.5 R116.2@1220,1100 v1(1250,1100) ; R145.2@1220,1362.5 v1(1250,1362.5) ; v1(1275,1462.5) C77.2@1315,1462.5 ; C125.2@1275,1870 v1(1275,1900) ; v1(1300,800) v1@1300,800.25 ; v1(1300,960) 1310,950 C53.2@1330,950 1330,990 C39.1@1315,1005 ; v1(1300,1400) C67.2@1330,1400 C38.2@1330,1362.5 ; C64.2@1330,787.5 1330,800.25 ; C51.2@1330,1175 1330,1135 C40.1@1315,1120 ; C78.2@1370,1325 1380,1335 v1(1400,1335) ; v1(1420,337.5) P2.4@1494,337.5 ; v1(1420,637.5) P2.16@1494,637.5 1496.5,635 1549.14,635 1555,629.14 1584.14,629.14 1595.61,640.61 1595.61,699.39 1557.5,737.5 P2.20@1494,737.5 ; v1(1450,975) C82.2@1480.75,975 C83.2@1480.75,937.38 C85.2@1480.75,900 ; v1(1450,1055.5) C54.2@1480.75,1055.5 ; v1(1450,1213) C87.2@1480.75,1213 C45.2@1480.75,1173.63 ; R49.1@1480,1337.5 1462.5,1337.5 1450,1325 v1(1450,1305) 1450,1290 1464,1276 C84.2@1480.75,1276 ; C44.2@1480.75,1016.13 C54.2@1480.75,1055.5 ; C69.1@1480.75,1134.25 C79.2@1480.75,1094.88 C54.2@1480.75,1055.5 ; C86.2@1480.75,1387.5 1480.75,1410 1488.47,1417.72 v1(1500,1417.72) 1507.72,1417.72 1520,1430 C71.1@1520,1450 ; P2.8@1494,437.5 1422.5,437.5 v1(1420,440) 1420,477.75 1429.75,487.5 P2.10@1494,487.5 P2.12@1494,537.5 ; C159.2@1562.5,1630 1562.5,1595 v1(1587.5,1570) ; C158.2@1562.5,1870 1595,1870 1613.09,1851.91 v1(1613.09,1800) ; C80.2@1626.77,1469.25 1626.77,1487.26 1630.86,1491.35 1630.86,1505.86 v1(1635,1510) ; C58.2@1674,1469.25 C106.2@1721.26,1469.25 1730.75,1469.25 1745,1455 v1(1800,1455) C56.1@1800,1374.75 ; C59.2@1712.5,755 C90.2@1750,755 C91.2@1787.5,755 C89.2@1825,755 C105.2@1862.5,755 C92.2@1900,755 ; C81.2@1863,1469.25 v1(1863,1500) ; v1(1900,725) C92.2@1900,755 ; C68.1@1926,1469.25 v1(1926,1500) ; R164.2@1937.5,657.5 v1(1937.5,725) ; v1(1975,1500) 1989,1486 C74.1@1989,1469.25 ; C164.2@1975,1610 v1(1975,1640) ; R54.1@2012.5,755 2012.5,734.75 2002.75,725 v1(1937.5,725) ; C161.2@2025,1610 C162.2@2075,1610 v1(2075,1640) ; C101.2@2050,755 2050,735 2060,725 v1(2080,725) 2090,715 C95.1@2125,715 2125,657.5 ; C102.2@2100,657.5 2125,657.5 ; v1(2125,1640) C170.2@2125,1610 C172.2@2175,1610 ; v1(2180,660) 2177.5,657.5 C103.2@2150,657.5 2125,657.5 ; C28.2@2220,1069.5 v1(2250,1069.5) C109.2@2280,1069.5 ; R22.1@2220,1118.5 v1(2250,1118.5) ; C75.1@2225,1870 v1(2225,1900) ; v1(2250,754.5) C113.2@2280,754.5 ; v1(2250,817.5) C112.2@2280,817.5 ; v1(2250,912) C111.2@2280,912 ; v1(2250,1006.5) C110.2@2280,1006.5 ; v1(2250,1164) C108.2@2280,1164 ; v1(2250,1227) C107.2@2280,1227 ; v1(2300,1400) 2320,1400 C145.2@2325,1405 ; C144.2@2325,1580 2405,1580 v2(2425,1600) ; v1(2480,835) C124.2@2480,864.75 R100.2@2480,912 ; C123.2@2520,959.25 2594.5,959.25 v1(2610.25,943.5) ; v2(2525,1650) C146.2@2525,1705 C148.2@2575,1705 ; C147.2@2575,1445 v2(2575,1500) ; v2(2575,1600) 2595,1620 C150.2@2675,1620 ; v2(2575,1650) C148.2@2575,1705 ; C151.2@2625,1405 R148.2@2675,1405 2685,1405 2700,1390 v1(2700,1370) ; R149.2@2625,1705 C148.2@2575,1705 ; C149.2@2675,1745 2690,1760 v1(2700,1760) ; C122.1@2710,662.5 2749.75,662.5 v1(2749.99,662.26) ; C118.1@2710,1287.5 v1(2750,1287.5) ; C121.2@2720,754.5 v1(2750,754.5) ; C120.2@2720,817.5 v1(2750,817.5) ; R99.1@2720,864.75 v1(2750,864.75) ; R96.1@2720,912 v1(2750,912) ; C119.2@2720,959.25 v1(2750,959.25) ; C117.2@2720,1006.5 v1(2750,1006.5) ; C116.2@2720,1101 v1(2750,1101) ; C115.2@2720,1164 v1(2750,1164) ; C114.2@2720,1227 v1(2750,1227) ; P10.9@2819.13,1336.38 2845,1336.38 2851.99,1343.37 2851.99,1363.01 v1(2840,1375) ; C76.1@2862.5,1870 v1(2862.5,1900) ; v1(2940,1830) C171.2@2975,1830 ; v1(2974.8,536.6) U8.1@3032.9,536.6 ; R53.2@3023.9,745 v1(3023.9,775) ; C35.2@3223.9,745 v1(3223.9,775) ; v1(3237.5,1360) 3267.53,1329.97 P10.6@3267.53,1199.28 ; v1(245,1160) 212.5,1160 R136.1@197.5,1175 212.5,1190 v1(245,1190) ; v1(245,1160) v1(245,1190) ; v1@1300,800.25 1300,835 C62.1@1315,850 1330,835 1330,800.25 ; v1@1300,800.25 1330,800.25 ; 1300,1062.5 v1(1300,1045) 1300,1020 C39.1@1315,1005 ; 1300,1062.5 v1(1300,1077.5) 1300,1105 C40.1@1315,1120 ; 1300,1062.5 C52.2@1330,1062.5 ; C39.1@1315,1005 1330,1020 C52.2@1330,1062.5 ; C40.1@1315,1120 1330,1105 C52.2@1330,1062.5 ; C92.2@1900,755 C104.2@1937.5,755 v1(1937.5,725) ; v1(1710,555) 1710,585.1 FB3.2@1725,600.1 1740,585.1 v1(1740,555) v1(1710,555)
  BOTTOM w25: P1.2@204,375 204,469 225,490 C2.1@290,490 ; v1(550,762.5) 550,725 ; U4.8@647.5,575 560,575 550,585 550,625 ; U4.7@647.5,625 550,625 ; U4.6@647.5,675 550,675 ; U4.5@647.5,725 550,725 ; 550,625 550,675 ; 550,675 550,725
  BOTTOM w30: P9.1@775,75 P9.2@775,175 ; P8.1@775,1975 P8.2@775,2075 ; P9.45@2975,75 P9.46@2975,175
  other v1: 1200,290 2358.25,723 2641.75,723 2358.25,786 2641.75,786 2358.25,849 2641.75,849 2389.75,943.5 2610.25,1038 2389.75,1069.5 2610.25,1101 2610.25,1132.5 2358.25,1195.5 2421.25,1195.5
  other v2: 840,550 890,550 3098.9,550 3148.9,550 840,600 890,600 3098.9,600 3148.9,600 987.5,1225 1025,1225 2425,1500 2475,1500 2525,1500 2475,1550 2525,1550 2575,1550 2475,1600 2525,1600 2475,1650
DVI_+5V: P6.19 R146.1 R147.1 RT1.2 | length 873.4
  BOTTOM w8: 3118.49,1064.88 3122.5,1060.87 P6.19@3145.08,1060.87
  BOTTOM w15: 2937.5,1062.5 R146.1@3005,1062.5 3005,1087.5 ; R147.1@3005,1112.5 3005,1087.5 ; 3118.49,1064.88 3095.87,1087.5 3005,1087.5
  BOTTOM w20: RT1.2@2775,525 2825,575 2825,950 2937.5,1062.5
EHRPWM1A: P9.14 U5.U14 | length 1650.6
  TOP w4.75: v1(1575,1500) 1585,1500 1642.5,1442.5 1642.5,1401.99 U5.U14@1658.27,1386.22
  LYR4 w5.25: P9.14@1375,175 1320.99,229.01 1320.99,640.99 1360,680 1360,906.18 1370,916.18 1370,1345 1426.51,1401.51 1461.51,1401.51 1470,1410 1470,1435 1525,1490 1565,1490 v1(1575,1500)
EHRPWM1B: P9.16 U5.T14 | length 1459.9
  TOP w4.75: v1(1642.5,1370.5) U5.T14@1658.27,1354.72
  LYR4 w5.25: P9.16@1475,175 1475,350 1400,425 1400,725 1436.49,761.49 1436.49,958.51 1430,965 1430,1310 1440.99,1320.99 1495.99,1320.99 1565,1390 1623,1390 v1(1642.5,1370.5)
EHRPWM2A: P8.19 U5.U10 | length 662
  TOP w4.75: P8.19@1675,1975 1755,1895 1755,1580 1817.99,1517.01 1817.99,1450.73 1800,1432.74 1800,1401.97 U5.U10@1784.25,1386.22
EHRPWM2B: P8.13 U5.T10 | length 1084.2
  TOP w4.75: v1(1768.5,1370.5) U5.T10@1784.25,1354.72
  LYR3 w5.25: P8.13@1375,1975 1260,1860 1260,1745 1270,1735 1270,1670 1285,1655 1625,1655 1685,1595 1685,1550 1710,1525 1710,1440 1768.5,1381.5 v1(1768.5,1370.5)
EMMC_RSTN: R111.2 R162.2 U13.K5 | length 190.8
  TOP w8: U13.K5@1125.79,1699.21 v3(1145.47,1718.9)
  BOTTOM w4.75: v3(1145.47,1718.9) 1145.47,1750 1150,1754.53 R111.2@1150,1830 R162.2@1200,1830
EMMC_VCCI: C125.1 U13.C2 | length 76.5
  TOP w4.75: U13.C2@1263.58,1758.27 v3(1273.43,1768.11)
  BOTTOM w4.75: v3(1273.43,1768.11) 1275,1769.68 C125.1@1275,1830
ENZ_KALDO_1P8V: R54.2 U5.B4 | length 135
  TOP w4.75: U5.B4@1973.23,913.78 v1(1989,898)
  BOTTOM w4.75: v1(1989,898) 2012.5,874.5 R54.2@2012.5,795
ETH_TXD4: R145.1 U14.18 | length 172.5
  TOP w4.75: U14.18@1036.75,1324 1036.75,1346.75 1052.5,1362.5 v1(1150,1362.5)
  BOTTOM w4.75: v1(1150,1362.5) R145.1@1180,1362.5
